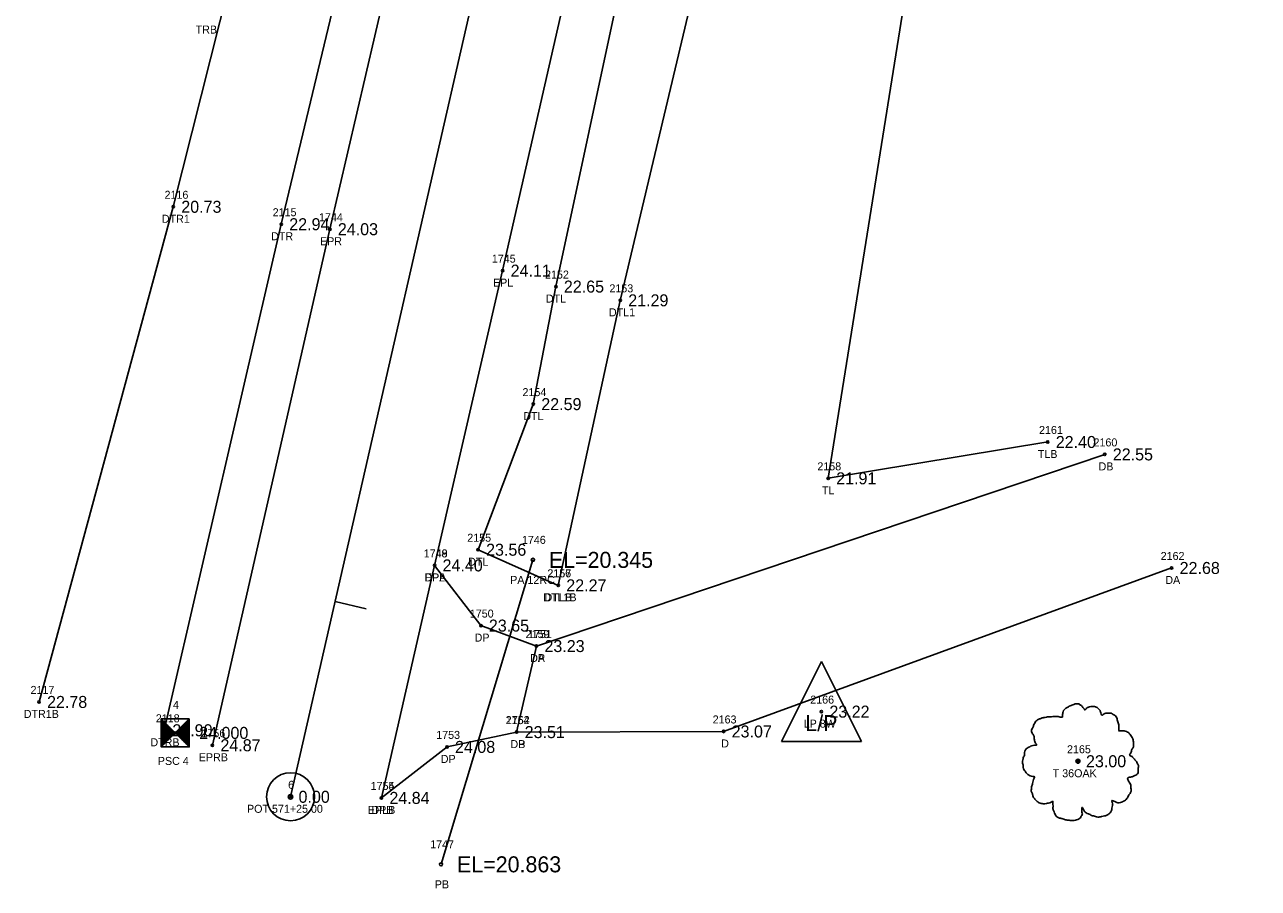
# Model space of a CAD drawing. Extents: x 2654414 to 2656963, y 761776 to 764965.
# Drawn here: x 2655350 to 2655504.2, y 761776.1 to 761884 of the extents above; entities that cross this region are included whole.
import ezdxf

# ---------------------------------------------------------------- set-up
doc = ezdxf.new("R2010")
doc.units = 0
for name, color, linetype in [('Default', 7, 'Continuous'), ('RD_EX_DR_Pipe', 7, 'Continuous'), ('RD_EX_DR_Pipe_txCode', 7, 'Continuous'), ('RD_EX_Driveway', 7, 'Continuous'), ('RD_EX_Driveway_txCode', 7, 'Continuous'), ('RD_EX_H2O', 7, 'Continuous'), ('RD_EX_H2O_txCode', 7, 'Continuous'), ('RD_EX_Road', 7, 'Continuous'), ('RD_EX_Road_txCode', 7, 'Continuous'), ('RD_EX_TX_Driveway_ELEV', 7, 'Continuous'), ('RD_EX_TX_H2O_ELEV', 7, 'Continuous'), ('RD_EX_TX_Road_ELEV', 7, 'Continuous'), ('RD_EX_TX_UT_ELEV', 7, 'Continuous'), ('RD_EX_TX_VEG_ELEV', 7, 'Continuous'), ('RD_EX_UT', 7, 'Continuous'), ('RD_EX_UT_txCode', 7, 'Continuous'), ('RD_EX_VEG', 7, 'Continuous'), ('RD_EX_VEG_txCode', 7, 'Continuous'), ('RD_HC_Cl', 7, 'Continuous'), ('RD_HC_Data', 7, 'Continuous'), ('RD_HC_Data_Tic', 7, 'Continuous'), ('RD_HC_Survey', 7, 'Continuous'), ('RD_HC_Survey_ELEV', 7, 'Continuous'), ('RD_HC_txCode', 7, 'Continuous'), ('RD_SMD_Locator', 7, 'Continuous'), ('RD_TX_Pipe_ElevEX', 7, 'Continuous')]:
    doc.layers.add(name, color=color, linetype=linetype)

msp = doc.modelspace()

# ---------------------------------------------------------------- linework, layer by layer
at = {"layer": 'Default'}
msp.add_line((2656050.51, 764712.37), (2655383.26, 761787.51), dxfattribs=at)
at = {"layer": 'RD_EX_DR_Pipe'}
msp.add_line((2655413.54, 761817.11), (2655402.06, 761779.07), dxfattribs=at)
at = {"layer": 'RD_EX_Driveway'}
msp.add_line((2655413.98, 761806.34), (2655484.99, 761830.29), dxfattribs=at)
for points in [[(2655401.25, 761816.42), (2655407.04, 761808.9), (2655413.98, 761806.34), (2655411.51, 761795.59), (2655402.81, 761793.74), (2655394.61, 761787.37)], [(2655493.34, 761816.1), (2655437.37, 761795.67), (2655411.51, 761795.59)]]:
    msp.add_lwpolyline(points, dxfattribs=at)
at = {"layer": 'RD_EX_H2O'}
for points in [[(2655450.32, 762170.31), (2655447.51, 762145.05), (2655428.44, 762061.32), (2655427.05, 762050.54), (2655425.43, 762042.76), (2655423.63, 762041.01), (2655404.09, 761950.81), (2655382.1, 761859.05), (2655367.49, 761795.82)], [(2655476.07, 762118.66), (2655457.95, 762043.6), (2655455.32, 762034.02), (2655437.36, 761949.13), (2655416.41, 761851.26), (2655413.59, 761836.57), (2655406.69, 761818.38), (2655416.71, 761813.93)], [(2655386.96, 762044.53), (2655409.62, 762037.18), (2655391.92, 761953.74), (2655368.61, 761861.23), (2655351.84, 761799.36)], [(2655458.25, 762004.65), (2655447.62, 761947.28), (2655424.45, 761849.54), (2655416.71, 761813.93)]]:
    msp.add_lwpolyline(points, dxfattribs=at)
at = {"layer": 'RD_EX_Road'}
for points in [[(2655700.99, 763232.28), (2655693.55, 763198.57), (2655671.65, 763102.04), (2655649.04, 763001.06), (2655627.27, 762906.23), (2655605, 762809.37), (2655598.99, 762783.09), (2655583.65, 762714.14), (2655561.97, 762618.32), (2655556.36, 762593.84), (2655548.11, 762557.14), (2655540.1, 762522.48), (2655518.03, 762425.04), (2655496.48, 762329.56), (2655475.55, 762236.62), (2655473.2, 762226.14), (2655466.57, 762197.5), (2655460.06, 762168.16), (2655454.26, 762143.78), (2655432.5, 762049.88), (2655410.7, 761955.51), (2655388.17, 761858.43), (2655373.5, 761793.95)], [(2655670.04, 762995.18), (2655648.57, 762900.67), (2655631.27, 762824.03), (2655626.67, 762802.87), (2655621.78, 762781.91), (2655611.71, 762738.43), (2655604.93, 762708.62), (2655582.64, 762610.54), (2655576.46, 762583.32), (2655561.41, 762517.24), (2655539.15, 762414.81), (2655531.98, 762386.15), (2655517.98, 762324.29), (2655508.17, 762280.15), (2655501.46, 762251.6), (2655496.92, 762232.09), (2655477.2, 762144.97), (2655472.14, 762122.52), (2655453.74, 762045.1), (2655431.79, 761949.92), (2655409.76, 761853.25), (2655401.25, 761816.42), (2655394.61, 761787.37)]]:
    msp.add_lwpolyline(points, dxfattribs=at)
at = {"layer": 'RD_EX_UT'}
for p, q in [((2655444.58, 761794.43), (2655449.58, 761804.43)), ((2655449.58, 761804.43), (2655454.58, 761794.43)), ((2655444.58, 761794.43), (2655454.58, 761794.43))]:
    msp.add_line(p, q, dxfattribs=at)
at = {"layer": 'RD_EX_VEG'}
msp.add_lwpolyline([(2655560.2, 762061.65), (2655512.87, 762073.11), (2655481.8, 762023.58), (2655450.43, 761827.3), (2655477.86, 761831.84)], dxfattribs=at)
for centre, radius in [((2655481.64, 761791.95), 0.25), ((2655481.62, 761791.93), 0.0001)]:
    msp.add_circle(centre, radius, dxfattribs=at)
for points in [[(2655481.77, 761799.11), (2655481.47, 761799.14), (2655481.14, 761799.04), (2655480.89, 761798.94), (2655480.67, 761798.86), (2655480.44, 761798.76), (2655480.14, 761798.59), (2655479.92, 761798.39), (2655479.79, 761798.14), (2655479.74, 761797.91), (2655479.69, 761797.64), (2655479.69, 761797.46), (2655479.57, 761797.44), (2655479.42, 761797.46), (2655479.17, 761797.54), (2655478.92, 761797.54), (2655478.67, 761797.54), (2655478.32, 761797.51), (2655477.97, 761797.51), (2655477.7, 761797.46), (2655477.37, 761797.41), (2655477, 761797.29), (2655476.65, 761797.16), (2655476.35, 761796.91), (2655476.1, 761796.44), (2655475.97, 761796.09), (2655475.82, 761795.84), (2655475.97, 761795.39), (2655476.15, 761795.04), (2655476.17, 761794.84), (2655476.25, 761794.42), (2655476.35, 761794.19), (2655476.47, 761793.99), (2655476.4, 761793.97), (2655476.02, 761793.92), (2655475.72, 761793.82), (2655475.3, 761793.59), (2655475.07, 761793.37), (2655474.97, 761793.04), (2655474.95, 761792.69), (2655474.85, 761792.49), (2655474.77, 761792.22), (2655474.75, 761792.14), (2655474.7, 761791.82), (2655474.8, 761791.37), (2655474.82, 761791.02), (2655474.95, 761790.79), (2655475.1, 761790.62), (2655475.27, 761790.37), (2655475.67, 761790.14), (2655476, 761790.04), (2655476.2, 761790.02), (2655476.02, 761789.52), (2655475.97, 761789.17), (2655475.85, 761788.77), (2655475.85, 761788.69), (2655475.8, 761788.22), (2655475.95, 761787.89), (2655476.02, 761787.52), (2655476.2, 761787.29), (2655476.47, 761786.99), (2655476.8, 761786.77), (2655477.3, 761786.64), (2655477.7, 761786.67), (2655478.27, 761786.84), (2655478.52, 761786.92), (2655478.49, 761786.74), (2655478.52, 761786.37), (2655478.52, 761785.94), (2655478.67, 761785.62), (2655478.77, 761785.34), (2655478.92, 761785.09), (2655479.24, 761784.87), (2655479.64, 761784.79), (2655480.07, 761784.64), (2655480.52, 761784.57), (2655481.02, 761784.54), (2655481.62, 761784.69), (2655481.89, 761784.82), (2655481.99, 761784.99), (2655482.19, 761785.37), (2655482.14, 761785.59), (2655482.17, 761786.19), (2655482.27, 761786.02), (2655482.44, 761785.67), (2655482.94, 761785.37), (2655483.34, 761785.19), (2655483.82, 761785.04), (2655484.12, 761784.97), (2655484.59, 761785.04), (2655484.97, 761785.12), (2655485.34, 761785.24), (2655485.64, 761785.52), (2655485.82, 761785.79), (2655485.87, 761786.07), (2655485.94, 761786.44), (2655485.99, 761786.62)], [(2655485.99, 761786.62), (2655485.92, 761786.79), (2655485.87, 761787.04), (2655485.94, 761787.02), (2655486.12, 761786.97), (2655486.39, 761786.84), (2655486.62, 761786.77), (2655486.94, 761786.79), (2655487.22, 761786.89), (2655487.67, 761787.17), (2655487.94, 761787.64), (2655488.22, 761788.04), (2655488.29, 761788.37), (2655488.24, 761788.59), (2655488.22, 761789.09), (2655488.02, 761789.34), (2655487.97, 761789.47), (2655487.87, 761789.87), (2655487.94, 761789.92), (2655488.22, 761789.97), (2655488.59, 761790.09), (2655488.87, 761790.22), (2655489.09, 761790.39), (2655489.17, 761790.62), (2655489.14, 761791.02), (2655489.19, 761791.42), (2655489.12, 761791.57), (2655489.02, 761791.72), (2655488.94, 761791.92), (2655488.79, 761792.07), (2655488.69, 761792.22), (2655488.59, 761792.32), (2655488.47, 761792.47), (2655488.29, 761792.59), (2655488.14, 761792.64), (2655488.09, 761792.79), (2655488.24, 761792.99), (2655488.29, 761793.09), (2655488.32, 761793.32), (2655488.54, 761793.67), (2655488.59, 761794.07), (2655488.54, 761794.49), (2655488.49, 761794.77), (2655488.34, 761795.04), (2655488.14, 761795.29), (2655488.02, 761795.47), (2655487.84, 761795.59), (2655487.52, 761795.72), (2655487.27, 761795.76), (2655486.92, 761795.76), (2655486.72, 761795.81), (2655486.74, 761795.86), (2655486.74, 761796.01), (2655486.74, 761796.29), (2655486.67, 761796.74), (2655486.52, 761797.24), (2655486.52, 761797.26), (2655486.42, 761797.51), (2655486.19, 761797.71), (2655486.02, 761797.81), (2655485.82, 761797.94), (2655485.57, 761797.96), (2655485.27, 761797.96), (2655484.99, 761797.91), (2655484.79, 761797.81), (2655484.62, 761797.69), (2655484.54, 761797.84), (2655484.44, 761798.14), (2655484.39, 761798.29), (2655484.24, 761798.46), (2655484.02, 761798.66), (2655483.57, 761798.79), (2655482.94, 761798.71), (2655482.64, 761798.51), (2655482.49, 761798.34), (2655482.44, 761798.46), (2655482.24, 761798.66), (2655482.14, 761798.84), (2655481.97, 761798.96), (2655481.82, 761799.06), (2655481.72, 761799.11)]]:
    msp.add_spline(points, degree=3, dxfattribs=at)
at = {"layer": 'RD_HC_Cl'}
msp.add_line((2656050.51, 764712.37), (2655383.26, 761787.51), dxfattribs=at)
at = {"layer": 'RD_HC_Data'}
for radius in [3, 0.282]:
    msp.add_circle((2655383.26, 761787.51), radius, dxfattribs=at)
at = {"layer": 'RD_HC_Data_Tic'}
msp.add_line((2655388.82, 761811.89), (2655392.72, 761811), dxfattribs=at)
at = {"layer": 'RD_HC_Survey'}
for p, q in [((2655367.1, 761797.24), (2655370.6, 761793.74)), ((2655370.6, 761797.24), (2655367.1, 761793.74)), ((2655367.13, 761797.22), (2655367.13, 761793.77)), ((2655367.15, 761797.19), (2655367.15, 761793.79)), ((2655367.17, 761797.17), (2655367.17, 761793.82)), ((2655367.2, 761797.14), (2655367.2, 761793.84)), ((2655367.22, 761797.12), (2655367.22, 761793.87)), ((2655367.25, 761797.09), (2655367.25, 761793.89)), ((2655367.27, 761797.07), (2655367.27, 761793.92)), ((2655367.3, 761797.04), (2655367.3, 761793.94)), ((2655367.32, 761797.02), (2655367.32, 761793.97)), ((2655367.35, 761797), (2655367.35, 761793.99)), ((2655367.37, 761796.97), (2655367.37, 761794.01)), ((2655367.4, 761796.95), (2655367.4, 761794.04)), ((2655367.42, 761796.92), (2655367.42, 761794.06)), ((2655367.45, 761796.9), (2655367.45, 761794.09)), ((2655367.47, 761796.87), (2655367.47, 761794.11)), ((2655367.5, 761796.85), (2655367.5, 761794.14)), ((2655367.52, 761796.82), (2655367.52, 761794.16)), ((2655367.55, 761796.8), (2655367.55, 761794.19)), ((2655367.57, 761796.77), (2655367.57, 761794.21)), ((2655367.6, 761796.75), (2655367.6, 761794.24)), ((2655367.62, 761796.72), (2655367.62, 761794.26)), ((2655367.65, 761796.7), (2655367.65, 761794.29)), ((2655367.67, 761796.67), (2655367.67, 761794.31)), ((2655367.69, 761796.65), (2655367.69, 761794.34)), ((2655367.72, 761796.62), (2655367.72, 761794.36)), ((2655367.74, 761796.6), (2655367.74, 761794.39)), ((2655367.77, 761796.57), (2655367.77, 761794.41)), ((2655367.79, 761796.55), (2655367.79, 761794.44)), ((2655367.82, 761796.52), (2655367.82, 761794.46)), ((2655367.84, 761796.5), (2655367.84, 761794.48)), ((2655367.87, 761796.48), (2655367.87, 761794.51)), ((2655367.89, 761796.45), (2655367.89, 761794.53)), ((2655367.92, 761796.43), (2655367.92, 761794.56)), ((2655367.94, 761796.4), (2655367.94, 761794.58)), ((2655367.97, 761796.38), (2655367.97, 761794.61)), ((2655367.99, 761796.35), (2655367.99, 761794.63)), ((2655368.02, 761796.33), (2655368.02, 761794.66)), ((2655368.04, 761796.3), (2655368.04, 761794.68)), ((2655368.07, 761796.28), (2655368.07, 761794.71)), ((2655368.09, 761796.25), (2655368.09, 761794.73)), ((2655368.12, 761796.23), (2655368.12, 761794.76)), ((2655368.14, 761796.2), (2655368.14, 761794.78)), ((2655368.16, 761796.18), (2655368.16, 761794.81)), ((2655368.19, 761796.15), (2655368.19, 761794.83)), ((2655368.21, 761796.13), (2655368.21, 761794.86)), ((2655368.24, 761796.1), (2655368.24, 761794.88)), ((2655368.26, 761796.08), (2655368.26, 761794.91)), ((2655368.29, 761796.05), (2655368.29, 761794.93)), ((2655368.31, 761796.03), (2655368.31, 761794.96)), ((2655368.34, 761796.01), (2655368.34, 761794.98)), ((2655368.36, 761795.98), (2655368.36, 761795)), ((2655368.39, 761795.96), (2655368.39, 761795.03)), ((2655368.41, 761795.93), (2655368.41, 761795.05)), ((2655368.44, 761795.91), (2655368.44, 761795.08)), ((2655368.46, 761795.88), (2655368.46, 761795.1)), ((2655368.49, 761795.86), (2655368.49, 761795.13)), ((2655368.51, 761795.83), (2655368.51, 761795.15)), ((2655369.19, 761795.83), (2655369.19, 761795.15)), ((2655369.21, 761795.86), (2655369.21, 761795.13)), ((2655369.24, 761795.88), (2655369.24, 761795.1)), ((2655369.26, 761795.91), (2655369.26, 761795.08)), ((2655369.29, 761795.93), (2655369.29, 761795.05)), ((2655369.31, 761795.96), (2655369.31, 761795.03)), ((2655369.34, 761795.98), (2655369.34, 761795)), ((2655369.36, 761796.01), (2655369.36, 761794.98)), ((2655369.39, 761796.03), (2655369.39, 761794.96)), ((2655369.41, 761796.05), (2655369.41, 761794.93)), ((2655369.44, 761796.08), (2655369.44, 761794.91)), ((2655369.46, 761796.1), (2655369.46, 761794.88)), ((2655369.49, 761796.13), (2655369.49, 761794.86)), ((2655369.51, 761796.15), (2655369.51, 761794.83)), ((2655369.54, 761796.18), (2655369.54, 761794.81)), ((2655369.56, 761796.2), (2655369.56, 761794.78)), ((2655369.59, 761796.23), (2655369.59, 761794.76)), ((2655369.61, 761796.25), (2655369.61, 761794.73)), ((2655369.64, 761796.28), (2655369.64, 761794.71)), ((2655369.66, 761796.3), (2655369.66, 761794.68)), ((2655369.68, 761796.33), (2655369.68, 761794.66)), ((2655369.71, 761796.35), (2655369.71, 761794.63)), ((2655369.73, 761796.38), (2655369.73, 761794.61)), ((2655369.76, 761796.4), (2655369.76, 761794.58)), ((2655369.78, 761796.43), (2655369.78, 761794.56)), ((2655369.81, 761796.45), (2655369.81, 761794.53)), ((2655369.83, 761796.48), (2655369.83, 761794.51)), ((2655369.86, 761796.5), (2655369.86, 761794.48)), ((2655369.88, 761796.52), (2655369.88, 761794.46)), ((2655369.91, 761796.55), (2655369.91, 761794.44)), ((2655369.93, 761796.57), (2655369.93, 761794.41)), ((2655369.96, 761796.6), (2655369.96, 761794.39)), ((2655369.98, 761796.62), (2655369.98, 761794.36)), ((2655370.01, 761796.65), (2655370.01, 761794.34)), ((2655370.03, 761796.67), (2655370.03, 761794.31)), ((2655370.06, 761796.7), (2655370.06, 761794.29)), ((2655370.08, 761796.72), (2655370.08, 761794.26)), ((2655370.11, 761796.75), (2655370.11, 761794.24)), ((2655370.13, 761796.77), (2655370.13, 761794.21)), ((2655370.16, 761796.8), (2655370.16, 761794.19)), ((2655370.18, 761796.82), (2655370.18, 761794.16)), ((2655370.2, 761796.85), (2655370.2, 761794.14)), ((2655370.23, 761796.87), (2655370.23, 761794.11)), ((2655370.25, 761796.9), (2655370.25, 761794.09)), ((2655370.28, 761796.92), (2655370.28, 761794.06)), ((2655370.3, 761796.95), (2655370.3, 761794.04)), ((2655370.33, 761796.97), (2655370.33, 761794.01)), ((2655370.35, 761797), (2655370.35, 761793.99)), ((2655370.38, 761797.02), (2655370.38, 761793.97)), ((2655370.4, 761797.04), (2655370.4, 761793.94)), ((2655370.43, 761797.07), (2655370.43, 761793.92)), ((2655370.45, 761797.09), (2655370.45, 761793.89)), ((2655370.48, 761797.12), (2655370.48, 761793.87)), ((2655370.5, 761797.14), (2655370.5, 761793.84)), ((2655370.53, 761797.17), (2655370.53, 761793.82)), ((2655370.55, 761797.19), (2655370.55, 761793.79)), ((2655370.58, 761797.22), (2655370.58, 761793.77)), ((2655368.54, 761795.81), (2655368.54, 761795.18)), ((2655368.56, 761795.78), (2655368.56, 761795.2)), ((2655368.59, 761795.76), (2655368.59, 761795.23)), ((2655368.61, 761795.73), (2655368.61, 761795.25)), ((2655368.64, 761795.71), (2655368.64, 761795.28)), ((2655368.66, 761795.68), (2655368.66, 761795.3)), ((2655368.68, 761795.66), (2655368.68, 761795.33)), ((2655368.71, 761795.63), (2655368.71, 761795.35)), ((2655368.73, 761795.61), (2655368.73, 761795.38)), ((2655368.76, 761795.58), (2655368.76, 761795.4)), ((2655368.78, 761795.56), (2655368.78, 761795.43)), ((2655368.81, 761795.53), (2655368.81, 761795.45)), ((2655368.83, 761795.51), (2655368.83, 761795.47)), ((2655368.87, 761795.51), (2655368.87, 761795.47)), ((2655368.89, 761795.53), (2655368.89, 761795.45)), ((2655368.92, 761795.56), (2655368.92, 761795.43)), ((2655368.94, 761795.58), (2655368.94, 761795.4)), ((2655368.97, 761795.61), (2655368.97, 761795.38)), ((2655368.99, 761795.63), (2655368.99, 761795.35)), ((2655369.02, 761795.66), (2655369.02, 761795.33)), ((2655369.04, 761795.68), (2655369.04, 761795.3)), ((2655369.07, 761795.71), (2655369.07, 761795.28)), ((2655369.09, 761795.73), (2655369.09, 761795.25)), ((2655369.12, 761795.76), (2655369.12, 761795.23)), ((2655369.14, 761795.78), (2655369.14, 761795.2)), ((2655369.17, 761795.81), (2655369.17, 761795.18))]:
    msp.add_line(p, q, dxfattribs=at)
msp.add_lwpolyline([(2655370.6, 761797.24), (2655367.1, 761797.24), (2655367.1, 761793.74), (2655370.6, 761793.74)], close=True, dxfattribs=at)
at = {"layer": 'RD_SMD_Locator'}
for centre, radius in [((2655368.61, 761861.23), 0.15), ((2655382.1, 761859.05), 0.15), ((2655388.17, 761858.43), 0.15), ((2655409.76, 761853.25), 0.15), ((2655416.41, 761851.26), 0.15), ((2655424.45, 761849.54), 0.15), ((2655413.59, 761836.57), 0.15), ((2655477.86, 761831.84), 0.15), ((2655484.99, 761830.29), 0.15), ((2655450.43, 761827.3), 0.15), ((2655406.69, 761818.38), 0.15), ((2655401.25, 761816.42), 0.15), ((2655401.25, 761816.42), 0.15), ((2655413.54, 761817.11), 0.2), ((2655493.34, 761816.1), 0.15), ((2655416.71, 761813.93), 0.15), ((2655416.71, 761813.93), 0.15), ((2655407.04, 761808.9), 0.15), ((2655413.98, 761806.34), 0.15), ((2655413.98, 761806.34), 0.15), ((2655351.84, 761799.36), 0.15), ((2655449.58, 761798.15), 0.15), ((2655367.49, 761795.82), 0.15), ((2655368.85, 761795.49), 0.15), ((2655411.51, 761795.59), 0.15), ((2655411.51, 761795.59), 0.15), ((2655437.37, 761795.67), 0.15), ((2655373.5, 761793.95), 0.15), ((2655402.81, 761793.74), 0.15), ((2655481.64, 761791.95), 0.15), ((2655383.26, 761787.51), 0.15), ((2655394.61, 761787.37), 0.15), ((2655394.61, 761787.37), 0.15), ((2655402.06, 761779.07), 0.2)]:
    msp.add_circle(centre, radius, dxfattribs=at)

# ---------------------------------------------------------------- texts
at = {"layer": 'RD_EX_DR_Pipe_txCode'}
for s, p in [('1746', (2655412.17, 761819.11)), ('PA 12RC', (2655410.7, 761814.11)), ('1747', (2655400.71, 761781.07)), ('PB', (2655401.28, 761776.07))]:
    msp.add_text(s, height=1, dxfattribs=at).set_placement(p)
at = {"layer": 'RD_EX_Driveway_txCode'}
for s, p in [('2160', (2655483.58, 761831.29)), ('DB', (2655484.21, 761828.29)), ('1749', (2655399.9, 761817.42)), ('2162', (2655491.97, 761817.1)), ('DPA', (2655399.98, 761814.42)), ('DA', (2655492.55, 761814.1)), ('1750', (2655405.66, 761809.9)), ('2159', (2655412.63, 761807.34)), ('1751', (2655412.92, 761807.34)), ('DP', (2655406.26, 761806.9)), ('DA', (2655413.18, 761804.34)), ('DP', (2655413.2, 761804.34)), ('2164', (2655410.14, 761796.59)), ('1752', (2655410.16, 761796.59)), ('2163', (2655436, 761796.67)), ('1753', (2655401.46, 761794.74)), ('DP', (2655410.73, 761793.59)), ('DB', (2655410.73, 761793.59)), ('D', (2655437.06, 761793.67)), ('DP', (2655402.03, 761791.74)), ('1754', (2655393.27, 761788.37)), ('DPB', (2655393.36, 761785.37))]:
    msp.add_text(s, height=1, dxfattribs=at).set_placement(p)
at = {"layer": 'RD_EX_H2O_txCode'}
for s, p in [('2116', (2655367.52, 761862.23)), ('2115', (2655381.03, 761860.05)), ('DTR1', (2655367.18, 761859.23)), ('DTR', (2655380.83, 761857.05)), ('2152', (2655415.06, 761852.26)), ('2153', (2655423.1, 761850.54)), ('DTL', (2655415.16, 761849.26)), ('DTL1', (2655423.04, 761847.54)), ('2154', (2655412.24, 761837.57)), ('DTL', (2655412.34, 761834.57)), ('2155', (2655405.34, 761819.38)), ('DTL', (2655405.45, 761816.38)), ('2156', (2655415.34, 761814.93)), ('2157', (2655415.36, 761814.93)), ('DTL1B', (2655414.83, 761811.93)), ('DTLB', (2655414.99, 761811.93)), ('2117', (2655350.78, 761800.36)), ('DTR1B', (2655349.93, 761797.36)), ('2118', (2655366.43, 761796.82)), ('DTRB', (2655365.75, 761793.82))]:
    msp.add_text(s, height=1, dxfattribs=at).set_placement(p)
at = {"layer": 'RD_EX_Road_txCode'}
for s, p in [('1744', (2655386.82, 761859.43)), ('EPR', (2655386.94, 761856.43)), ('1745', (2655408.41, 761854.25)), ('EPL', (2655408.55, 761851.25)), ('1748', (2655399.9, 761817.42)), ('EPL', (2655400.04, 761814.42)), ('1756', (2655372.13, 761794.95)), ('EPRB', (2655371.8, 761791.95)), ('1755', (2655393.27, 761788.37)), ('EPLB', (2655392.93, 761785.37))]:
    msp.add_text(s, height=1, dxfattribs=at).set_placement(p)
at = {"layer": 'RD_EX_TX_Driveway_ELEV'}
for s, p in [('22.55', (2655485.99, 761829.54)), ('24.40', (2655402.25, 761815.67)), ('22.68', (2655494.34, 761815.35)), ('23.65', (2655408.04, 761808.15)), ('23.23', (2655414.98, 761805.59)), ('23.23', (2655414.98, 761805.59)), ('23.51', (2655412.51, 761794.84)), ('23.51', (2655412.51, 761794.84)), ('23.07', (2655438.37, 761794.92)), ('24.08', (2655403.81, 761792.99)), ('24.84', (2655395.61, 761786.62))]:
    msp.add_text(s, height=1.5, dxfattribs=at).set_placement(p)
at = {"layer": 'RD_EX_TX_H2O_ELEV'}
for s, p in [('20.73', (2655369.61, 761860.48)), ('22.94', (2655383.1, 761858.3)), ('22.65', (2655417.41, 761850.51)), ('21.29', (2655425.45, 761848.79)), ('22.59', (2655414.59, 761835.82)), ('23.56', (2655407.69, 761817.63)), ('22.27', (2655417.71, 761813.18)), ('22.27', (2655417.71, 761813.18)), ('22.78', (2655352.84, 761798.61)), ('23.90', (2655368.49, 761795.07))]:
    msp.add_text(s, height=1.5, dxfattribs=at).set_placement(p)
at = {"layer": 'RD_EX_TX_Road_ELEV'}
for s, p in [('24.03', (2655389.17, 761857.68)), ('24.11', (2655410.76, 761852.5)), ('24.40', (2655402.25, 761815.67)), ('24.87', (2655374.5, 761793.2)), ('24.84', (2655395.61, 761786.62))]:
    msp.add_text(s, height=1.5, dxfattribs=at).set_placement(p)
at = {"layer": 'RD_EX_TX_UT_ELEV'}
msp.add_text('23.22', height=1.5, dxfattribs=at).set_placement((2655450.58, 761797.4))
at = {"layer": 'RD_EX_TX_VEG_ELEV'}
for s, p in [('22.40', (2655478.86, 761831.09)), ('21.91', (2655451.43, 761826.55)), ('23.00', (2655482.64, 761791.2))]:
    msp.add_text(s, height=1.5, dxfattribs=at).set_placement(p)
at = {"layer": 'RD_EX_UT'}
msp.add_text('L/P', height=2, dxfattribs=at).set_placement((2655447.57, 761795.71))
at = {"layer": 'RD_EX_UT_txCode'}
for s, p in [('2166', (2655448.19, 761799.15)), ('LP 8W', (2655447.37, 761796.15))]:
    msp.add_text(s, height=1, dxfattribs=at).set_placement(p)
at = {"layer": 'RD_EX_VEG_txCode'}
for s, p in [('TRB', (2655371.41, 761882.87)), ('2161', (2655476.77, 761832.84)), ('TLB', (2655476.62, 761829.84)), ('2158', (2655449.08, 761828.3)), ('TL', (2655449.66, 761825.3)), ('2165', (2655480.27, 761792.95)), ('T 36OAK', (2655478.48, 761789.95))]:
    msp.add_text(s, height=1, dxfattribs=at).set_placement(p)
at = {"layer": 'RD_HC_Survey_ELEV'}
for s, p in [('24.000', (2655371.85, 761794.74)), ('0.00', (2655384.26, 761786.76))]:
    msp.add_text(s, height=1.5, dxfattribs=at).set_placement(p)
at = {"layer": 'RD_HC_txCode'}
for s, p in [('4', (2655368.57, 761798.49)), ('PSC 4', (2655366.68, 761791.49)), ('6', (2655382.96, 761788.51)), ('POT 571+25.00', (2655377.82, 761785.51))]:
    msp.add_text(s, height=1, dxfattribs=at).set_placement(p)
at = {"layer": 'RD_TX_Pipe_ElevEX'}
for s, p in [('EL=20.345', (2655415.54, 761816.11)), ('EL=20.863', (2655404.06, 761778.07))]:
    msp.add_text(s, height=2, dxfattribs=at).set_placement(p)

doc.saveas('drawing.dxf')
